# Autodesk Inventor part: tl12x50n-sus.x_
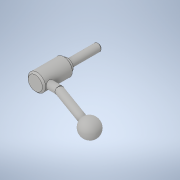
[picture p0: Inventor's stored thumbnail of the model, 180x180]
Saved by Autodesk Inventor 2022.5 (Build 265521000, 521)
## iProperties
Created: 2021-02
Part Number: tl12x50n-sus.x_
Material: 一般
Document SubType Name: Modeling
Designer: ImaoCorp
Density: 1 g/cm^3
Appearance: 既定
Sending System: SOLIDWORKS 2019-2019304
MC: AMD64
MC_MODEL: Intel64 Family 6 Model 60 Stepping 3, GenuineIntel
OS: Windows_NT
FRU: Parasolid Version 31.0, build 290,  9- 1-2019
FORMAT: text
GUISE: transmit
KEY: tl12x50n-sus
FILE: tl12x50n-sus.x_t
DATE: Mon Feb 22 14:52:21 2021
Author: ImaoCorp
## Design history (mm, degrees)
feature "Base1"
node "ソリッド1"
